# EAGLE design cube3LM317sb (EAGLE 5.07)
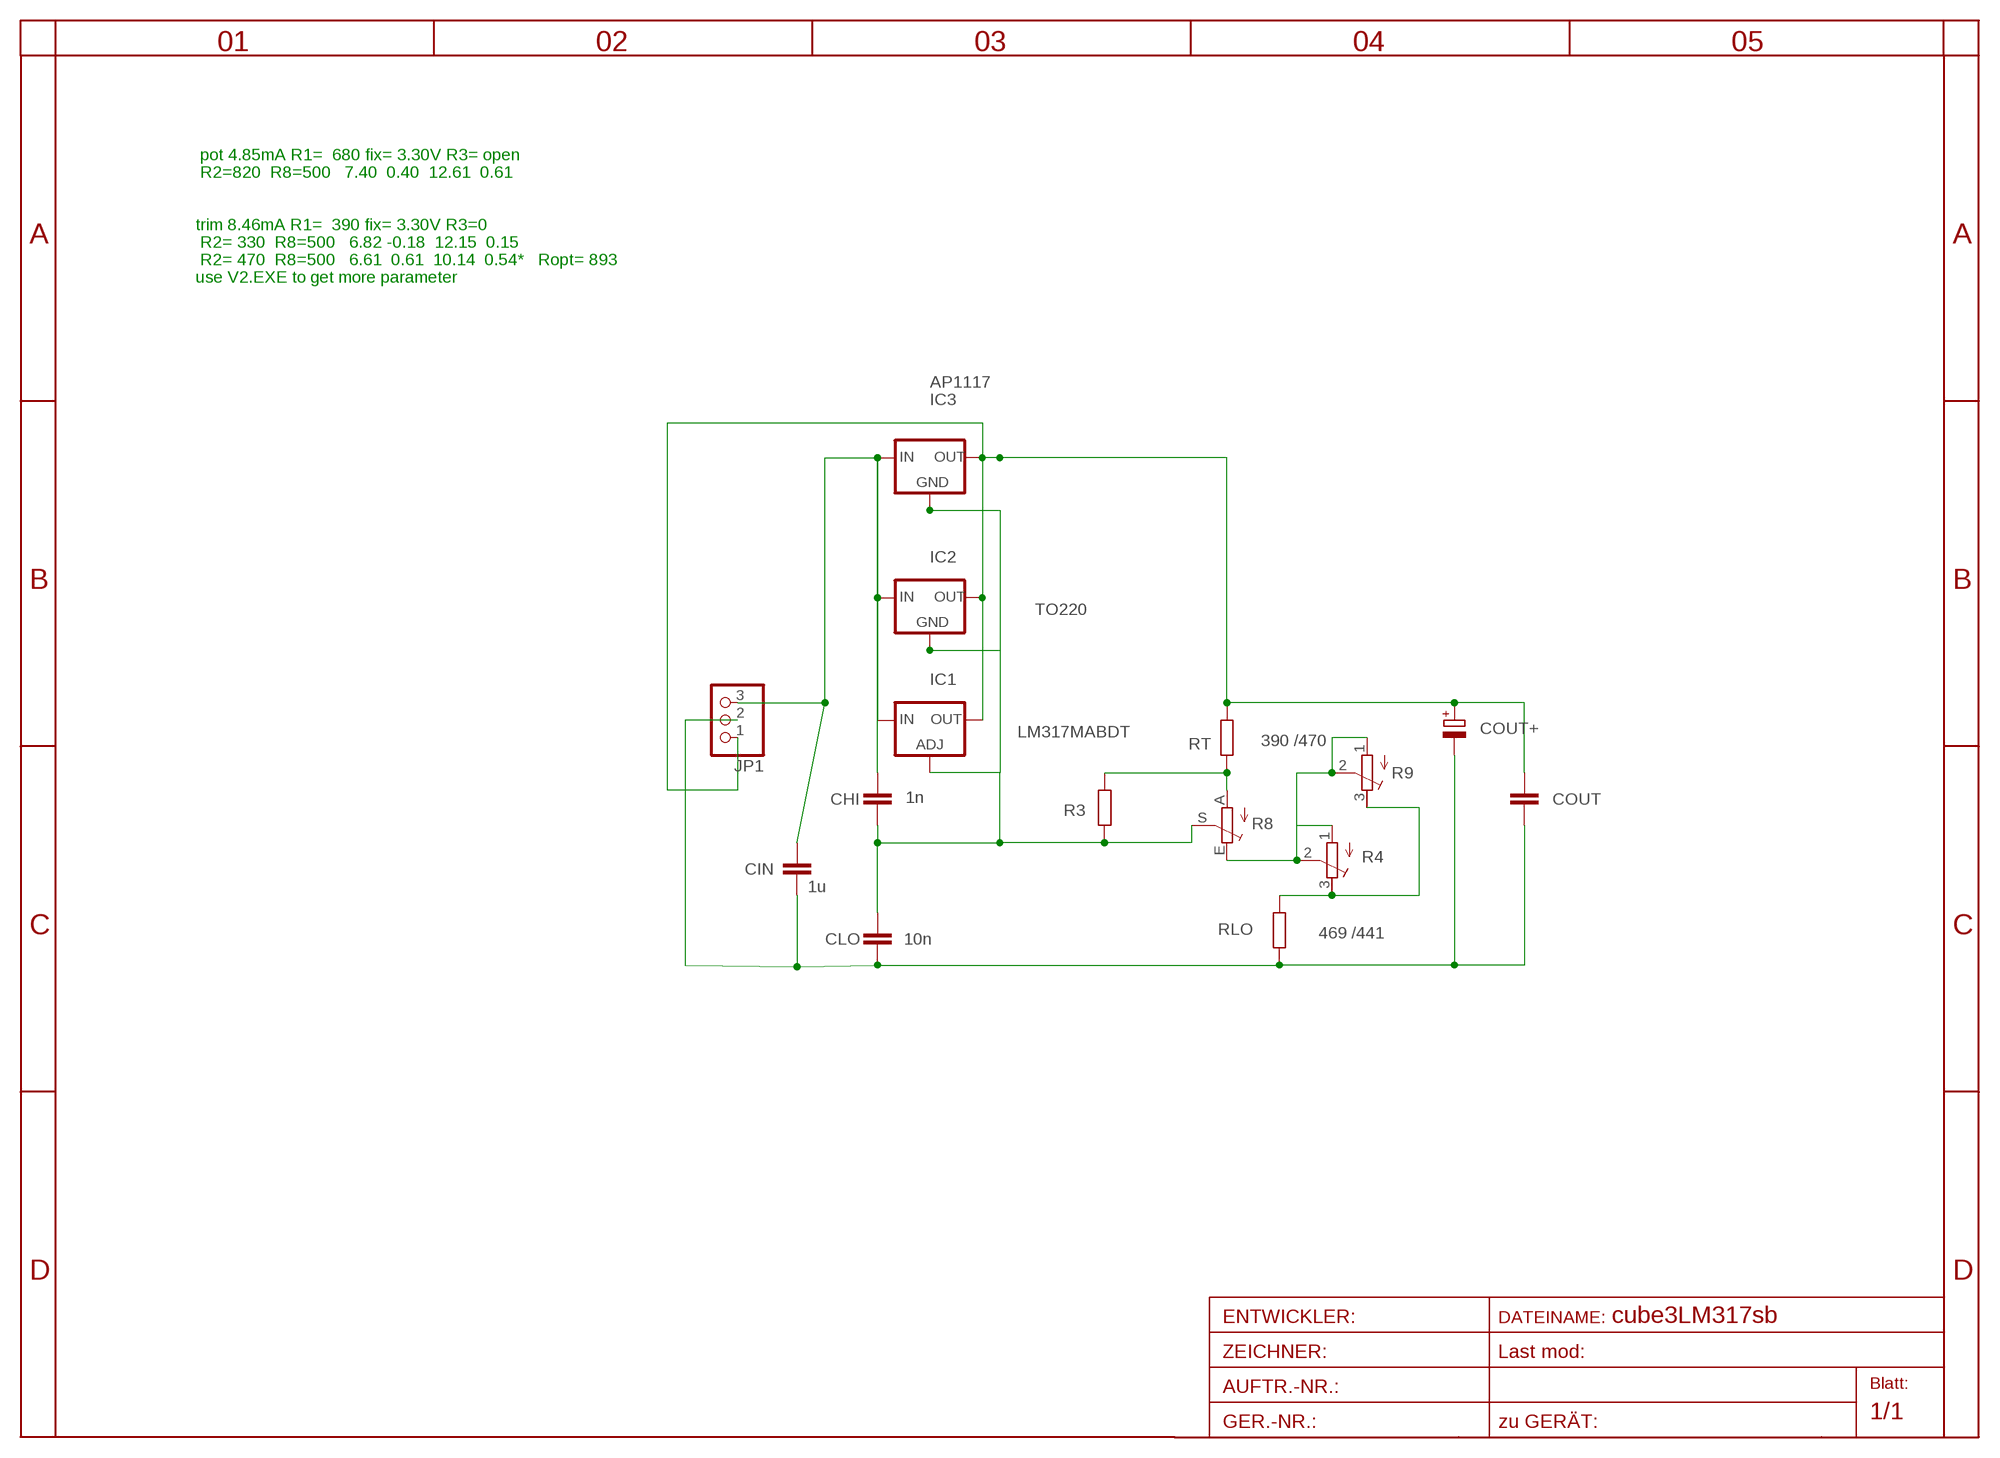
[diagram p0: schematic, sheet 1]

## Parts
CHI  1n  C-EUC0805  [C0805]
CIN  1u  C-EUC1206  [C1206]
CLO  10n  C-EUC0805  [C0805]
COUT  C-EUC1206  [C1206]
COUT+  CPOL-EUE2.5-6  [E2,5-6]
IC1  LM317MABDT  [DPACK]
IC2  TO220  78XXS  [78XXS]
IC3  AP1117  [SOT223]
JP1  PINHD-1X3  [1X03]
R3  R-EU_R0603  [R0603]
R4  R-TRIMM3202  [RTRIM3202]
R8  TRIM_EU-RAND160  [RANDL]
R9  R-TRIMM3374  [RTRIM3374]
RLO  469 /441  R-EU_R1206  [R1206]
RT  390 /470  R-EU_R0805  [R0805]

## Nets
GND: CIN.2 CLO.2 COUT+.- COUT.2 JP1.2 RLO.1
IN: CHI.1 CIN.1 IC1.3(IN) IC2.IN IC3.3(IN) JP1.3
N$1: R4.1(E) R4.2(S) R8.E R9.1(E) R9.2(S)
N$4: CHI.2 CLO.1 IC1.1(ADJ) IC2.GND IC3.1(GND) R3.1 R8.S
N$6: R4.3(A) R9.3(A) RLO.2
N$7: R3.2 R8.A RT.1
OUT: COUT+.+ COUT.1 IC1.4(OUT) IC2.OUT IC3.2(OUT) IC3.4(TAB) JP1.1 RT.2

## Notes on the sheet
- pot 4.85mA R1=  680 fix= 3.30V R3= open
- R2=820  R8=500   7.40  0.40  12.61  0.61
- trim 8.46mA R1=  390 fix= 3.30V R3=0
- R2= 330  R8=500   6.82 -0.18  12.15  0.15
- R2= 470  R8=500   6.61  0.61  10.14  0.54*   Ropt= 893
- use V2.EXE to get more parameter

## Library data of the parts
CHI CIN CLO COUT = rcl:C-EU: CAPACITOR, European symbol
COUT+ = rcl:CPOL-EU: POLARIZED CAPACITOR, European symbol
IC1 = v-reg:LM317?*: 500 mA Adjustable Output Positive Voltage Regulator Source: http://www.onsemi.co.jp .. LM317M-D.PDF
IC2 = v-reg:78XXS: VOLTAGE REGULATOR
IC3 = v-reg:AP1117
JP1 = pinhead:PINHD-1X3: PIN HEADER
R3 RLO RT = rcl:R-EU_: RESISTOR, European symbol
R4 R9 = rcl:R-TRIMM: Trimm resistor
R8 = pot:TRIM_EU-: POTENTIOMETER

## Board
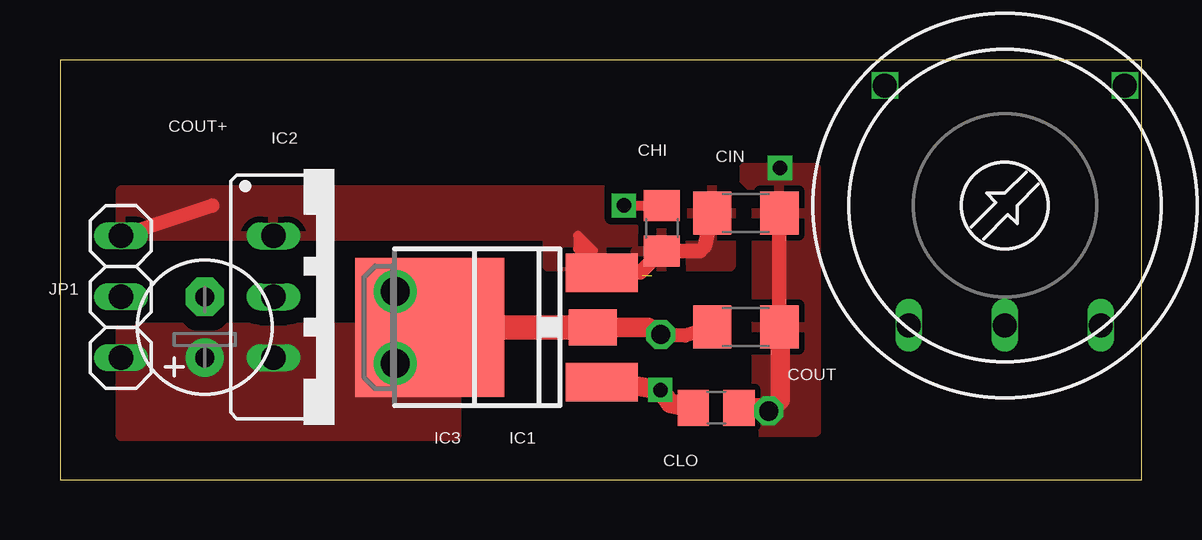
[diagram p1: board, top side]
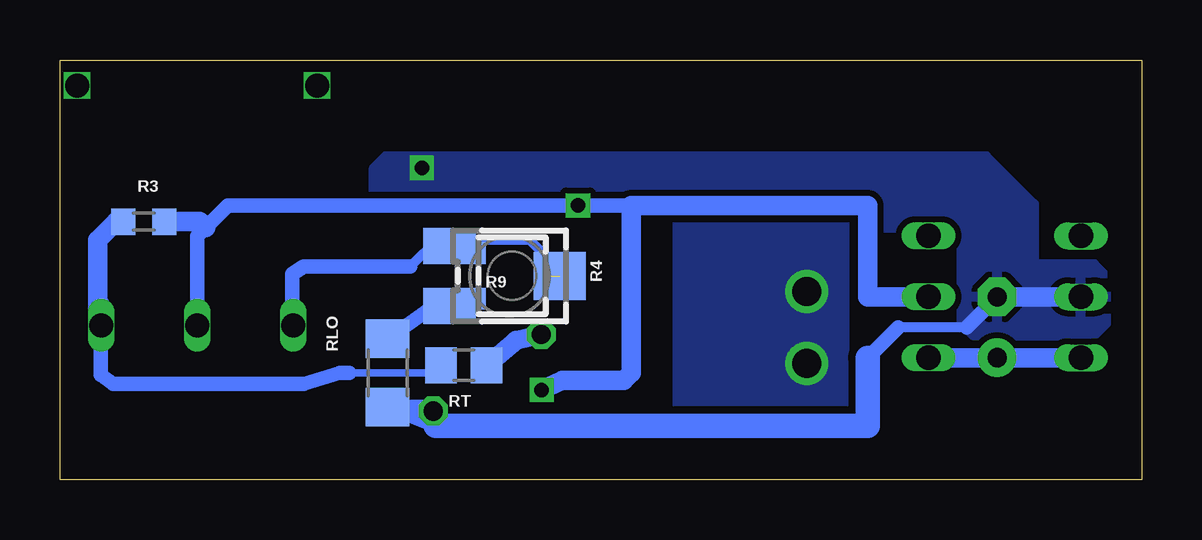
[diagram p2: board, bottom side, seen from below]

Size 45.08 x 17.5 mm. Coordinates in mm from the lower left corner, seen from the top.
Outline: 0,0 45.08,0 45.08,17.5 0,17.5 0,0
Copper layers (1*16): Top 0.035mm / dielectric 1.5mm / Bottom 0.035mm
Design rules "default": minimum track width 10mil, minimum drill 20mil, track to track 8mil, track to pad 8mil, pad to pad 8mil, via to via 8mil, smd to smd 8mil, copper to edge 40mil, drill to drill 8mil, minimum pad ring 1mil, minimum via ring 8mil, stop-mask expansion 4mil, vias tented up to drill 0mil, thermal gap 10mil

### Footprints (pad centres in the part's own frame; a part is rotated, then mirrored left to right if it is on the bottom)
C0805 = smd 1.3 x 1.5: 1 -0.95,0; 2 0.95,0
C1206 = smd 1.6 x 1.8: 1 -1.4,0; 2 1.4,0
E2,5-6 = drill 0.8 pad 1.6 round: + -1.27,0 | drill 0.8 pad 1.6 octagon: - 1.27,0
DPACK = smd 1.6 x 3: 1 -2.28,-4.8; 3 2.28,-4.8 | smd 5.8 x 6.2: 4 0,2.38
78XXS = drill 1.016 long: GND 0,-2.54; IN -2.54,-2.54; OUT 2.54,-2.54
SOT223 = smd 1.5 x 2: 1 -2.3,-3.15; 2 0,-3.15; 3 2.3,-3.15 | smd 3.8 x 2: 4 0,3.15
1X03 = drill 1.016 long: 1 -2.54,0; 2 0,0; 3 2.54,0
R0603 = smd 1 x 1.1: 1 -0.85,0; 2 0.85,0
RTRIM3202 = smd 0.9 x 1.3: 1 -0.95,-1.75; 3 0.95,-1.75 | smd 1.6 x 1.4: 2 0,1.6
RANDL = drill 1 long: A -4,5; E 4,5; S 0,5 | drill 1 square: P$1 -5,-5; P$2 5,-5
RTRIM3374 = smd 1.5 x 2.2: 1 -1.25,-2.5; 3 1.25,-2.5 | smd 1.98 x 2.17: 2 0,2.1
R1206 = smd 1.6 x 1.803: 1 -1.422,0; 2 1.422,0
R0805 = smd 1.3 x 1.5: 1 -0.95,0; 2 0.95,0

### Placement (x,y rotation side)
CHI  25.08,10.48 90 top
CIN  28.57,11.11 0 top
CLO  27.34,3 0 top
COUT  28.57,6.37 0 top
COUT+  6.03,6.35 90 top
IC1  17.78,6.35 90 top
IC2  11.43,7.62 270 top
IC3  19.05,6.35 90 top
JP1  2.54,7.62 90 top
R3  41.59,10.76 180 bottom
R4  26.25,8.5 270 bottom
R8  39.37,11.43 180 top
R9  26.35,8.49 270 bottom
RLO  31.43,4.45 90 bottom
RT  28.26,4.76 0 bottom

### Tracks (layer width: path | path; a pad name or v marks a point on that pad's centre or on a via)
GND  (via drill 0.6, 0.8)
  Top 0.61: COUT.2 CIN.2
  Top 0.813: COUT.2 30,6.67 30,3.33 v29.53,2.86 29.39,3 CLO.2
  Bottom 0.406: 7.3,6.35 10.16,6.35
  Bottom 0.61: 10.16,6.35 11.43,5.08 | COUT+.- 7.3,6.35 | v29.53,2.86 29.69,3.02 RLO.1 29.43,2.24
  Bottom 0.813: JP1.2 COUT+.-
  Bottom 1.016: 11.43,5.08 11.43,2.24 29.43,2.24
  other vias: 30,13
  pour Top: 29.5,2 31.5,2 31.5,13 28.5,13 28.5,12.5 29,12 29,2
  pour Bottom (isolate 0.254): 1.5,7 1.5,6.5 2,6 7,6 7.5,6.5 7.5,10 8,10.5 31.5,10.5 32,11 32,13 31.5,13.5 6.5,13.5 4.5,11.5 4.5,9 2,9 1.5,8.5 1.5,8 1.5,7.5
IN
  Top 0.406: 26.67,9.53 26.86,9.71 | CHI.1 | IC3.3 22.2,9.55 21.59,10.16 21.59,9.62 IC1.3
  Top 0.61: JP1.3 6.35,11.43 | IC1.3 24.18,8.63 CHI.1 | 26.86,9.71 CIN.1 | CHI.1 26.67,9.53
  Top 0.813: IC2.IN 8.26,10.16
  pour Top (isolate 0.305): 27.94,12.06 27.94,8.89 20.32,8.89 20.32,10.16 2.54,10.16 2.54,12.06
N$1  (1 unrouted)
  Bottom 0.406: R4.2 24.65,9.15 25.5,10 28.55,10 | 28.59,10 R9.1 | 28.59,10 29.37,10 30.48,8.89 | 28.55,10 28.59,10 | 28.55,10 R4.1
  Bottom 0.61: 30.48,8.89 34.92,8.89 35.41,8.57 35.41,6.62 R8.E
N$4  (via drill 0.6)
  Top 0.406: v23.5,11.43 CHI.2 | IC1.1 22.22,4.07 IC3.1
  Top 0.813: IC3.1 22.33,4.18 v25.01,3.73 25.43,3.18 CLO.1
  Bottom 0.61: 20.32,11.43 v23.5,11.43 38.1,11.43 39.02,10.52 39.37,10.16 R8.S
  Bottom 0.813: IC2.GND 11.43,7.62 11.43,11.43 20.32,11.43 21.27,11.43 21.27,4.45 21.59,4.13 24.16,4.13 v25.01,3.73 | R3.1 39.26,10.76 39.02,10.52
N$6
  Bottom 0.406: R9.3 28.31,7.24 R4.3
  Bottom 0.61: RLO.2 29.21,7.45 R9.3
N$7
  Bottom 0.305: 29.21,4.45 33.02,4.45
  Bottom 0.61: RT.1 29.21,4.45 | 33.02,4.45 33.42,4.45 34.92,3.99 42.86,3.99 43.38,4.36 43.38,5.79 R8.A 43.37,7.01 43.35,7.38
  Bottom 0.813: R3.2 42.74,10.76 43.5,10 43.5,6.56 R8.A
OUT  (via drill 0.8, 1.2)
  Top 0.61: COUT.1 26.05,6.02 v25.03,6.05
  Top 0.813: IC3.2 24.5,6.35 v25.03,6.05
  Top 1.016: IC1.4 IC3.2
  Bottom 0.813: JP1.1 IC2.OUT | RT.2 26.07,5.8 v25.03,6.05
  other vias: 13.97,4.85 13.97,7.85
  pour Top (isolate 0.61, no thermals): 2.54,6.35 16.51,6.35 16.51,1.81 2.54,1.81
  pour Bottom (isolate 0.305): 19.37,11.1 19.37,3.17 12.38,3.17 12.38,10.79 12.06,11.1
